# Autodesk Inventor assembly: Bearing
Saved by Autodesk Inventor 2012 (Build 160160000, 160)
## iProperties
Created: 2011-12
Part Number: Bearing
Document SubType Name: Assembly
Designer: Admin
ClientObjectVersion: 1
Author: Admin
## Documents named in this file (2)
- C:\Documents and Settings\All Users\Autodesk Learning\Inventor 2009\Advanced Assembly and Machine Design\Workspace\GearBox-A\Design Accelerator\Bearing2.iam
- C:\Documents and Settings\All Users\Autodesk Learning\Inventor 2009\Advanced Assembly and Machine Design\Libraries\Content Center Files\en-US\DIN 615\DIN 615 - L 25 - 25 x 52 x 15.ipt
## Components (1 placed, 1 different names)
1. DIN 615 L 25 - 25 x 52 x 15:1
